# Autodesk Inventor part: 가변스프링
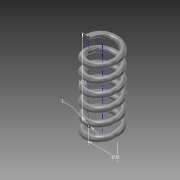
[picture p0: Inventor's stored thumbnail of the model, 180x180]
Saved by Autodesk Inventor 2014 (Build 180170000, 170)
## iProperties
Created: 2015-12
Part Number: 가변스프링
Material: 강철, 탄소
Document SubType Name: Modeling
Designer: test_01
Density: 7.87 g/cm^3
Appearance: 반연마
Mass: 16.5234 g
Surface Area: 28.4907 cm^2
Volume: 2.09954 cm^3
Author: test_01
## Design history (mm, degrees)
sketch "스케치1"
  geometry: L1 (0, 0)-(8, 0); L2 (8, 0)-(8, 42); L3 (8, 42)-(0, 42); L4 (0, 42)-(0, 0); C1 r 1.5 at (8, 0)
  constraints: 8 end point, 2 parallel, 1 centre point, 1 coincident, 1 horizontal, 1 perpendicular
  dimensions: "d0" = 16 diameter of L2 L4; "d1" = 42 distance of L1.end L2.end (derived); "d2" = 3 diameter of C1
feature "코일1" pitch "d3" = 10; turns "d5" = 6; dims "d4" = 42 (= d1), "d6" = 0, angle "d7" = 90 deg, angle "d8" = 90 deg, "d9" = 0, "d10" = 0
sketch "스케치2"
  geometry: L1 (-9.5, 0)-(-6.5, 0) reference; 1 further point
  constraints: 1 horizontal alignment
extrude "돌출1" cut sketch "스케치2" distance "d11" = 10; taper "d12" = 0 deg
node "작업 평면1"
sketch "스케치3"
  geometry: L1 (-1.5, 0)-(1.5, 0) reference; 1 further point
  constraints: 1 horizontal alignment
extrude "돌출2" cut sketch "스케치3" distance "d14" = 10; taper "d15" = 0 deg
node "솔리드1"
node "절단 모서리 투영1"
node "절단 모서리 투영2"
other parameters: "d13" = 90 deg
